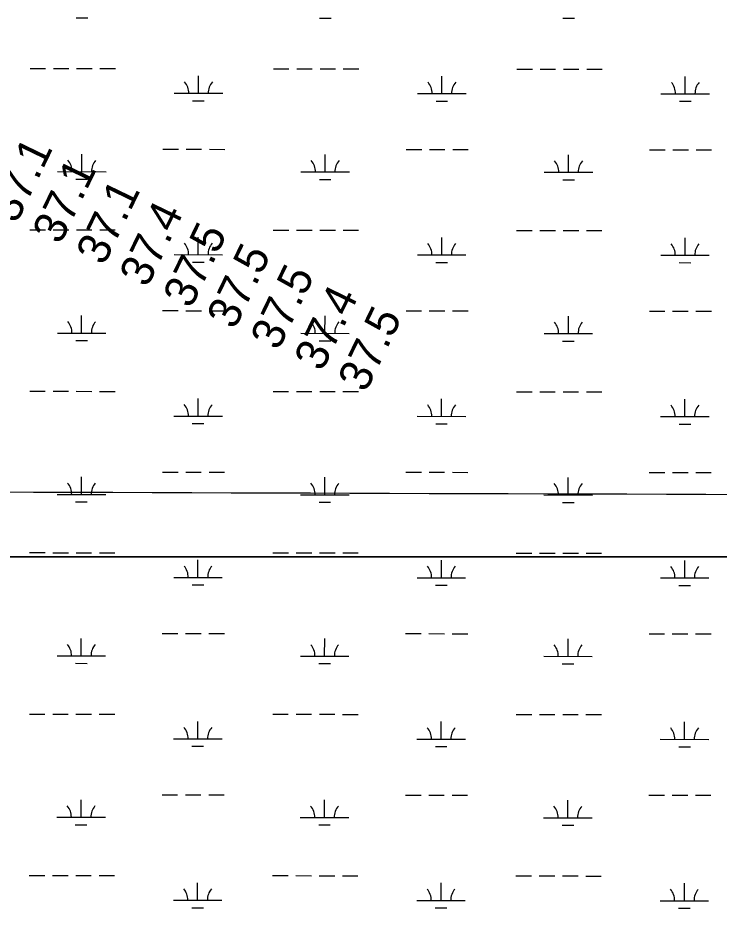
# Model space of a CAD drawing. Extents: x 3148686 to 3186545, y 916144 to 941516.
# Drawn here: x 3163759 to 3165206, y 926722 to 928557 of the extents above; entities that cross this region are included whole.
import ezdxf

# ---------------------------------------------------------------- set-up
doc = ezdxf.new("R2010")
doc.units = 0
for name, color, linetype in [('V-GRID-MAJR', 7, 'Continuous'), ('V-RIVR-RANG', 7, 'Continuous'), ('V-SITE-VEGE', 7, 'Continuous'), ('V-WETL-SWMP', 7, 'Continuous')]:
    doc.layers.add(name, color=color, linetype=linetype)

msp = doc.modelspace()

# ---------------------------------------------------------------- linework, layer by layer
at = {"layer": 'V-GRID-MAJR'}
msp.add_spline([(3152944, 927616.7), (3155553.9, 927607.5), (3160773.9, 927589.6), (3165993.8, 927572.5), (3171213.8, 927556.2), (3176433.8, 927540.7), (3181653.7, 927525.9), (3184263.7, 927518.7)], degree=3, dxfattribs=at)
at = {"layer": 'V-SITE-VEGE'}
for points in [[(3160193.2, 927446.3), (3165314.7, 927446.3)], [(3165314.7, 927446.3), (3160193.2, 927446.3)]]:
    msp.add_lwpolyline(points, dxfattribs=at)
at = {"layer": 'V-WETL-SWMP'}
for p, q in [((3163879.4, 928557.3), (3163903.4, 928557.2)), ((3164381.3, 928556.7), (3164405.3, 928556.7)), ((3164883.2, 928556.2), (3164907.2, 928556.2)), ((3163784.5, 928452.7), (3163816.5, 928452.7)), ((3163832.5, 928452.7), (3163864.5, 928452.6)), ((3163880.5, 928452.6), (3163912.5, 928452.6)), ((3163928.5, 928452.6), (3163960.5, 928452.5)), ((3164286.4, 928452.2), (3164318.4, 928452.2)), ((3164334.4, 928452.1), (3164366.4, 928452.1)), ((3164382.4, 928452.1), (3164414.4, 928452.1)), ((3164430.4, 928452), (3164462.4, 928452)), ((3164788.3, 928451.7), (3164820.3, 928451.6)), ((3164836.3, 928451.6), (3164868.3, 928451.6)), ((3164884.3, 928451.6), (3164916.3, 928451.5)), ((3164932.3, 928451.5), (3164964.3, 928451.5)), ((3164131.7, 928401.6), (3164131.8, 928437.6)), ((3164633.6, 928401.1), (3164633.7, 928437.1)), ((3165135.5, 928400.6), (3165135.6, 928436.6)), ((3164081.7, 928401.7), (3164181.7, 928401.6)), ((3164583.6, 928401.1), (3164683.6, 928401)), ((3165085.5, 928400.6), (3165185.5, 928400.5)), ((3164119.7, 928386.2), (3164143.7, 928386.2)), ((3164621.6, 928385.7), (3164645.6, 928385.6)), ((3165123.5, 928385.1), (3165147.5, 928385.1)), ((3164058.2, 928286.3), (3164090.2, 928286.2)), ((3164106.2, 928286.2), (3164138.2, 928286.2)), ((3164154.2, 928286.2), (3164186.2, 928286.1)), ((3164560.1, 928285.7), (3164592.1, 928285.7)), ((3164608.1, 928285.7), (3164640.1, 928285.6)), ((3164656.1, 928285.6), (3164688.1, 928285.6)), ((3165062, 928285.2), (3165094, 928285.2)), ((3165110, 928285.2), (3165142, 928285.1)), ((3165158, 928285.1), (3165190, 928285.1)), ((3163891.1, 928240), (3163891.1, 928276)), ((3164393, 928239.5), (3164393, 928275.5)), ((3164894.9, 928238.9), (3164894.9, 928274.9)), ((3163841.1, 928240.1), (3163941.1, 928240)), ((3163879.1, 928224.6), (3163903.1, 928224.6)), ((3164343, 928239.5), (3164443, 928239.4)), ((3164381, 928224.1), (3164405, 928224)), ((3164844.9, 928239), (3164944.9, 928238.9)), ((3164882.9, 928223.5), (3164906.9, 928223.5)), ((3163784.1, 928120), (3163816.1, 928120)), ((3163832.1, 928120), (3163864.1, 928120)), ((3163880.1, 928119.9), (3163912.1, 928119.9)), ((3163928.1, 928119.9), (3163960.1, 928119.9)), ((3164286, 928119.5), (3164318, 928119.5)), ((3164334, 928119.5), (3164366, 928119.4)), ((3164382, 928119.4), (3164414, 928119.4)), ((3164430, 928119.4), (3164462, 928119.3)), ((3164787.9, 928119), (3164819.9, 928119)), ((3164835.9, 928118.9), (3164867.9, 928118.9)), ((3164883.9, 928118.9), (3164915.9, 928118.9)), ((3164931.9, 928118.8), (3164963.9, 928118.8)), ((3164131.4, 928068.9), (3164131.4, 928104.9)), ((3164633.3, 928068.4), (3164633.3, 928104.4)), ((3165135.2, 928067.9), (3165135.2, 928103.9)), ((3164081.4, 928069), (3164181.4, 928068.9)), ((3164583.3, 928068.5), (3164683.3, 928068.4)), ((3165085.2, 928067.9), (3165185.2, 928067.8)), ((3164119.3, 928053.5), (3164143.3, 928053.5)), ((3164621.3, 928053), (3164645.3, 928053)), ((3165123.2, 928052.5), (3165147.2, 928052.4)), ((3164057.8, 927953.6), (3164089.8, 927953.6)), ((3164105.8, 927953.5), (3164137.8, 927953.5)), ((3164153.8, 927953.5), (3164185.8, 927953.5)), ((3164559.7, 927953.1), (3164591.7, 927953)), ((3164607.7, 927953), (3164639.7, 927953)), ((3164655.7, 927953), (3164687.7, 927952.9)), ((3165061.7, 927952.5), (3165093.6, 927952.5)), ((3165109.6, 927952.5), (3165141.6, 927952.4)), ((3165157.6, 927952.4), (3165189.6, 927952.4)), ((3163890.7, 927907.3), (3163890.8, 927943.3)), ((3164392.6, 927906.8), (3164392.7, 927942.8)), ((3164894.5, 927906.3), (3164894.6, 927942.3)), ((3163840.7, 927907.4), (3163940.7, 927907.3)), ((3164342.6, 927906.9), (3164442.6, 927906.7)), ((3164844.5, 927906.3), (3164944.5, 927906.2)), ((3163878.7, 927891.9), (3163902.7, 927891.9)), ((3164380.6, 927891.4), (3164404.6, 927891.4)), ((3164882.5, 927890.9), (3164906.5, 927890.8)), ((3163783.8, 927787.4), (3163815.8, 927787.3)), ((3163831.8, 927787.3), (3163863.8, 927787.3)), ((3163879.8, 927787.3), (3163911.8, 927787.2)), ((3163927.8, 927787.2), (3163959.8, 927787.2)), ((3164285.7, 927786.8), (3164317.7, 927786.8)), ((3164333.7, 927786.8), (3164365.7, 927786.8)), ((3164381.7, 927786.7), (3164413.7, 927786.7)), ((3164429.7, 927786.7), (3164461.7, 927786.7)), ((3164787.6, 927786.3), (3164819.6, 927786.3)), ((3164835.6, 927786.3), (3164867.6, 927786.2)), ((3164883.6, 927786.2), (3164915.6, 927786.2)), ((3164931.6, 927786.2), (3164963.6, 927786.1)), ((3164131, 927736.3), (3164131.1, 927772.3)), ((3164632.9, 927735.7), (3164633, 927771.7)), ((3165134.8, 927735.2), (3165134.9, 927771.2)), ((3164081, 927736.3), (3164181, 927736.2)), ((3164582.9, 927735.8), (3164682.9, 927735.7)), ((3165084.8, 927735.3), (3165184.8, 927735.2)), ((3164119, 927720.8), (3164143, 927720.8)), ((3164620.9, 927720.3), (3164644.9, 927720.3)), ((3165122.8, 927719.8), (3165146.8, 927719.8)), ((3164057.5, 927620.9), (3164089.5, 927620.9)), ((3164105.5, 927620.9), (3164137.5, 927620.8)), ((3164153.5, 927620.8), (3164185.5, 927620.8)), ((3164559.4, 927620.4), (3164591.4, 927620.3)), ((3164607.4, 927620.3), (3164639.4, 927620.3)), ((3164655.4, 927620.3), (3164687.4, 927620.2)), ((3165061.3, 927619.9), (3165093.3, 927619.8)), ((3165109.3, 927619.8), (3165141.3, 927619.8)), ((3165157.3, 927619.8), (3165189.3, 927619.7)), ((3163890.4, 927574.7), (3163890.4, 927610.7)), ((3164392.3, 927574.1), (3164392.3, 927610.1)), ((3164894.2, 927573.6), (3164894.2, 927609.6)), ((3163840.4, 927574.7), (3163940.4, 927574.6)), ((3164342.3, 927574.2), (3164442.3, 927574.1)), ((3164844.2, 927573.7), (3164944.2, 927573.5)), ((3163878.4, 927559.2), (3163902.4, 927559.2)), ((3164380.3, 927558.7), (3164404.3, 927558.7)), ((3164882.2, 927558.2), (3164906.2, 927558.2)), ((3163783.4, 927454.7), (3163815.4, 927454.7)), ((3163831.4, 927454.6), (3163863.4, 927454.6)), ((3163879.4, 927454.6), (3163911.4, 927454.6)), ((3163927.4, 927454.5), (3163959.4, 927454.5)), ((3164285.3, 927454.2), (3164317.3, 927454.1)), ((3164333.3, 927454.1), (3164365.3, 927454.1)), ((3164381.3, 927454.1), (3164413.3, 927454)), ((3164429.3, 927454), (3164461.3, 927454)), ((3164787.2, 927453.6), (3164819.2, 927453.6)), ((3164835.2, 927453.6), (3164867.2, 927453.6)), ((3164883.2, 927453.5), (3164915.2, 927453.5)), ((3164931.2, 927453.5), (3164963.2, 927453.5)), ((3164130.7, 927403.6), (3164130.7, 927439.6)), ((3164632.6, 927403.1), (3164632.6, 927439.1)), ((3165134.5, 927402.5), (3165134.5, 927438.5)), ((3164080.7, 927403.6), (3164180.7, 927403.5)), ((3164582.6, 927403.1), (3164682.6, 927403)), ((3165084.5, 927402.6), (3165184.5, 927402.5)), ((3164118.6, 927388.2), (3164142.6, 927388.1)), ((3164620.6, 927387.6), (3164644.6, 927387.6)), ((3165122.5, 927387.1), (3165146.5, 927387.1)), ((3164057.1, 927288.2), (3164089.1, 927288.2)), ((3164105.1, 927288.2), (3164137.1, 927288.2)), ((3164153.1, 927288.1), (3164185.1, 927288.1)), ((3164559, 927287.7), (3164591, 927287.7)), ((3164607, 927287.7), (3164639, 927287.6)), ((3164655, 927287.6), (3164687, 927287.6)), ((3163890, 927242), (3163890.1, 927278)), ((3164391.9, 927241.5), (3164392, 927277.5)), ((3164893.8, 927240.9), (3164893.9, 927276.9)), ((3165060.9, 927287.2), (3165092.9, 927287.1)), ((3165108.9, 927287.1), (3165140.9, 927287.1)), ((3165156.9, 927287.1), (3165188.9, 927287)), ((3163840, 927242), (3163940, 927241.9)), ((3164341.9, 927241.5), (3164441.9, 927241.4)), ((3164843.8, 927241), (3164943.8, 927240.9)), ((3163878, 927226.6), (3163902, 927226.5)), ((3164379.9, 927226), (3164403.9, 927226)), ((3164881.8, 927225.5), (3164905.8, 927225.5)), ((3163783.1, 927122), (3163815.1, 927122)), ((3163831.1, 927122), (3163863.1, 927121.9)), ((3163879.1, 927121.9), (3163911.1, 927121.9)), ((3163927.1, 927121.9), (3163959.1, 927121.8)), ((3164130.3, 927070.9), (3164130.4, 927106.9)), ((3164285, 927121.5), (3164317, 927121.5)), ((3164333, 927121.4), (3164365, 927121.4)), ((3164381, 927121.4), (3164413, 927121.4)), ((3164429, 927121.3), (3164461, 927121.3)), ((3164632.2, 927070.4), (3164632.3, 927106.4)), ((3164786.9, 927121), (3164818.9, 927120.9)), ((3164834.9, 927120.9), (3164866.9, 927120.9)), ((3164882.9, 927120.9), (3164914.9, 927120.8)), ((3164930.9, 927120.8), (3164962.9, 927120.8)), ((3165134.1, 927069.9), (3165134.2, 927105.9)), ((3164080.3, 927071), (3164180.3, 927070.9)), ((3164582.2, 927070.4), (3164682.2, 927070.3)), ((3165084.1, 927069.9), (3165184.1, 927069.8)), ((3164118.3, 927055.5), (3164142.3, 927055.5)), ((3164620.2, 927055), (3164644.2, 927054.9)), ((3165122.1, 927054.4), (3165146.1, 927054.4)), ((3163889.7, 926909.3), (3163889.7, 926945.3)), ((3164056.8, 926955.6), (3164088.8, 926955.5)), ((3164104.8, 926955.5), (3164136.8, 926955.5)), ((3164152.8, 926955.5), (3164184.8, 926955.4)), ((3164391.6, 926908.8), (3164391.6, 926944.8)), ((3164558.7, 926955), (3164590.7, 926955)), ((3164606.7, 926955), (3164638.7, 926954.9)), ((3164654.7, 926954.9), (3164686.7, 926954.9)), ((3164893.5, 926908.2), (3164893.5, 926944.2)), ((3165060.6, 926954.5), (3165092.6, 926954.5)), ((3165108.6, 926954.5), (3165140.6, 926954.4)), ((3165156.6, 926954.4), (3165188.6, 926954.4)), ((3163839.7, 926909.4), (3163939.7, 926909.3)), ((3164341.6, 926908.8), (3164441.6, 926908.7)), ((3164843.5, 926908.3), (3164943.5, 926908.2)), ((3163877.7, 926893.9), (3163901.7, 926893.9)), ((3164379.6, 926893.4), (3164403.6, 926893.3)), ((3164881.5, 926892.8), (3164905.5, 926892.8)), ((3163782.7, 926789.3), (3163814.7, 926789.3)), ((3163830.7, 926789.3), (3163862.7, 926789.3)), ((3163878.7, 926789.2), (3163910.7, 926789.2)), ((3163926.7, 926789.2), (3163958.7, 926789.2)), ((3164130, 926738.2), (3164130, 926774.2)), ((3164284.6, 926788.8), (3164316.6, 926788.8)), ((3164332.6, 926788.8), (3164364.6, 926788.7)), ((3164380.6, 926788.7), (3164412.6, 926788.7)), ((3164428.6, 926788.7), (3164460.6, 926788.6)), ((3164631.9, 926737.7), (3164631.9, 926773.7)), ((3164786.5, 926788.3), (3164818.5, 926788.3)), ((3164834.5, 926788.2), (3164866.5, 926788.2)), ((3164882.5, 926788.2), (3164914.5, 926788.2)), ((3164930.5, 926788.1), (3164962.5, 926788.1)), ((3165133.8, 926737.2), (3165133.8, 926773.2)), ((3164080, 926738.3), (3164180, 926738.2)), ((3164581.9, 926737.8), (3164681.9, 926737.7)), ((3165083.8, 926737.2), (3165183.8, 926737.1)), ((3164117.9, 926722.8), (3164141.9, 926722.8)), ((3164619.9, 926722.3), (3164643.9, 926722.3)), ((3165121.8, 926721.8), (3165145.8, 926721.7))]:
    msp.add_line(p, q, dxfattribs=at)
for centre, start, end in [((3164076.5, 928402.1), 359.1678, 40.7115), ((3164187, 928402), 139.1678, 180.7115), ((3164578.4, 928401.6), 359.1678, 40.7115), ((3164688.9, 928401.5), 139.1678, 180.7115), ((3165080.3, 928401.1), 359.1678, 40.7115), ((3165190.8, 928401), 139.1678, 180.7115), ((3163835.8, 928240.5), 359.1678, 40.7115), ((3163946.3, 928240.4), 139.1678, 180.7115), ((3164337.7, 928240), 359.1678, 40.7115), ((3164448.2, 928239.9), 139.1678, 180.7115), ((3164839.6, 928239.5), 359.1678, 40.7115), ((3164950.1, 928239.4), 139.1678, 180.7115), ((3164076.1, 928069.5), 359.1678, 40.7115), ((3164186.6, 928069.4), 139.1678, 180.7115), ((3164578, 928068.9), 359.1678, 40.7115), ((3164688.5, 928068.8), 139.1678, 180.7115), ((3165079.9, 928068.4), 359.1678, 40.7115), ((3165190.4, 928068.3), 139.1678, 180.7115), ((3163835.5, 927907.9), 359.1678, 40.7115), ((3163946, 927907.7), 139.1678, 180.7115), ((3164337.4, 927907.3), 359.1678, 40.7115), ((3164447.9, 927907.2), 139.1678, 180.7115), ((3164839.3, 927906.8), 359.1678, 40.7115), ((3164949.8, 927906.7), 139.1678, 180.7115), ((3164075.8, 927736.8), 359.1678, 40.7115), ((3164186.3, 927736.7), 139.1678, 180.7115), ((3164577.7, 927736.3), 359.1678, 40.7115), ((3164688.2, 927736.2), 139.1678, 180.7115), ((3165079.6, 927735.7), 359.1678, 40.7115), ((3165190.1, 927735.6), 139.1678, 180.7115), ((3163835.1, 927575.2), 359.1678, 40.7115), ((3163945.6, 927575.1), 139.1678, 180.7115), ((3164337, 927574.7), 359.1678, 40.7115), ((3164447.5, 927574.5), 139.1678, 180.7115), ((3164838.9, 927574.1), 359.1678, 40.7115), ((3164949.4, 927574), 139.1678, 180.7115), ((3164075.4, 927404.1), 359.1678, 40.7115), ((3164185.9, 927404), 139.1678, 180.7115), ((3164577.3, 927403.6), 359.1678, 40.7115), ((3164687.8, 927403.5), 139.1678, 180.7115), ((3165079.2, 927403.1), 359.1678, 40.7115), ((3165189.7, 927402.9), 139.1678, 180.7115), ((3163834.8, 927242.5), 359.1678, 40.7115), ((3163945.3, 927242.4), 139.1678, 180.7115), ((3164336.7, 927242), 359.1678, 40.7115), ((3164447.2, 927241.9), 139.1678, 180.7115), ((3164838.6, 927241.5), 359.1678, 40.7115), ((3164949.1, 927241.3), 139.1678, 180.7115), ((3164075.1, 927071.4), 359.1678, 40.7115), ((3164185.6, 927071.3), 139.1678, 180.7115), ((3164577, 927070.9), 359.1678, 40.7115), ((3164687.5, 927070.8), 139.1678, 180.7115), ((3165078.9, 927070.4), 359.1678, 40.7115), ((3165189.4, 927070.3), 139.1678, 180.7115), ((3163834.4, 926909.8), 359.1678, 40.7115), ((3163944.9, 926909.7), 139.1678, 180.7115), ((3164336.3, 926909.3), 359.1678, 40.7115), ((3164446.8, 926909.2), 139.1678, 180.7115), ((3164838.2, 926908.8), 359.1678, 40.7115), ((3164948.7, 926908.7), 139.1678, 180.7115), ((3164074.7, 926738.8), 359.1678, 40.7115), ((3164185.2, 926738.7), 139.1678, 180.7115), ((3164576.6, 926738.2), 359.1678, 40.7115), ((3164687.1, 926738.1), 139.1678, 180.7115), ((3165078.5, 926737.7), 359.1678, 40.7115), ((3165189, 926737.6), 139.1678, 180.7115)]:
    msp.add_arc(centre, 35.2, start, end, dxfattribs=at)

# ---------------------------------------------------------------- texts
at = {"layer": 'V-RIVR-RANG'}
for s, p in [('37.1', (3163756.4, 928131)), ('37.1', (3163846.6, 928087.8)), ('37.1', (3163936.7, 928044.5)), ('37.4', (3164025.9, 927999.1)), ('37.5', (3164116, 927955.8)), ('37.5', (3164206.2, 927912.6)), ('37.5', (3164296.3, 927869.3)), ('37.4', (3164386.5, 927826)), ('37.5', (3164476.6, 927782.8))]:
    msp.add_text(s, height=67, rotation=64.2183, dxfattribs=at).set_placement(p)

doc.saveas('drawing.dxf')
